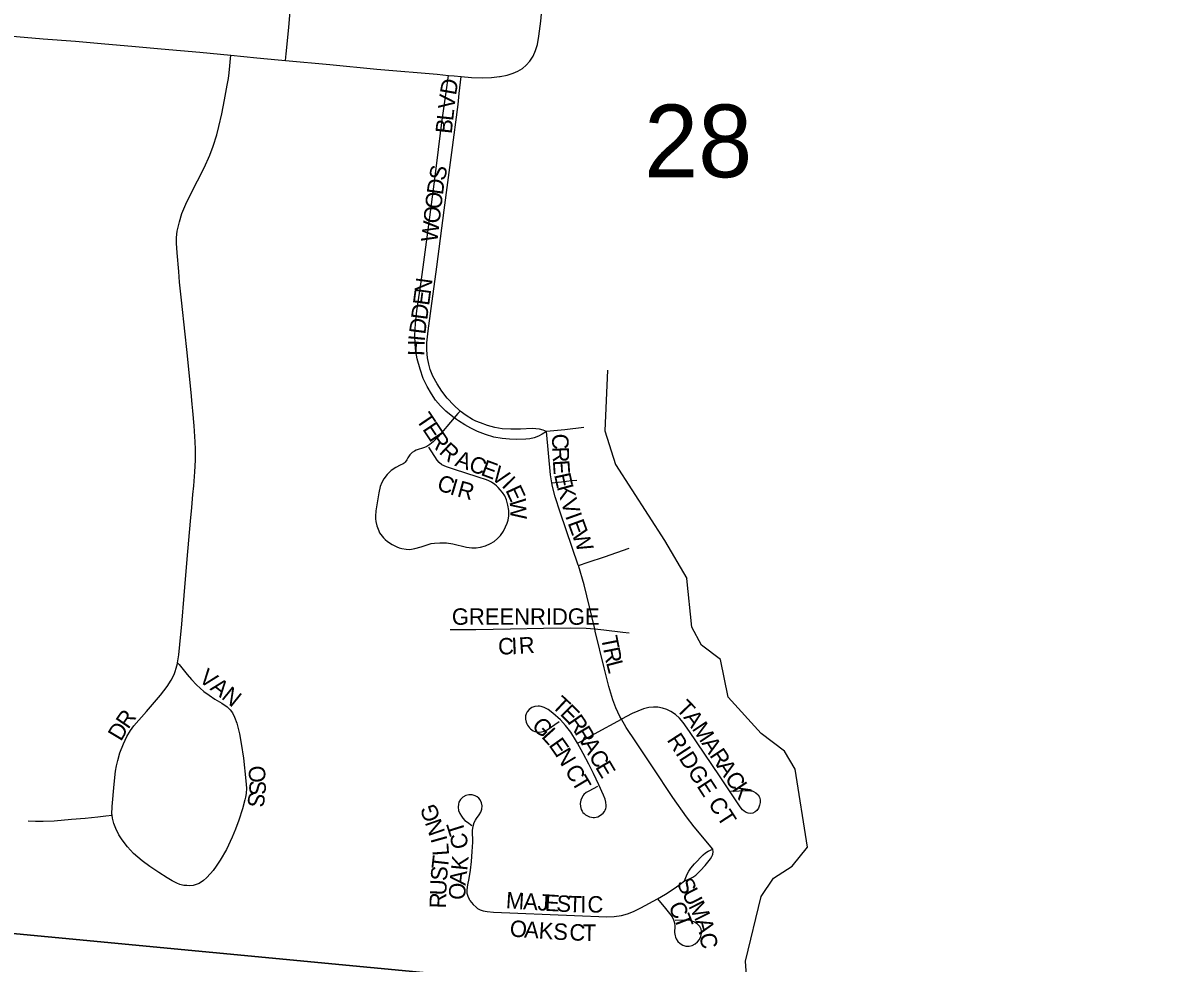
# Model space of a CAD drawing. Extents: x 1410790 to 1770854, y 448063 to 770588.
# Drawn here: x 1535566 to 1539019, y 639877 to 642738 of the extents above; entities that cross this region are included whole.
import ezdxf

# ---------------------------------------------------------------- set-up
doc = ezdxf.new("R2010")
doc.units = 0
for name, color, linetype in [('GM_X_City_Street', 7, 'Continuous'), ('GM_X_City_Street_Text', 7, 'Continuous'), ('GM_X_Minor_River', 7, 'Continuous'), ('GM_X_Section', 7, 'Continuous'), ('GM_X_Section_Text', 7, 'Continuous')]:
    doc.layers.add(name, color=color, linetype=linetype)

msp = doc.modelspace()

# ---------------------------------------------------------------- linework, layer by layer
at = {"layer": 'GM_X_City_Street'}
for points in [[(1536365.5, 642623), (1536367.5, 642643), (1536375.7, 642723.7), (1536382.9, 642812), (1536388.7, 642887.1), (1536391.7, 642922.9), (1536395.8, 642971.8), (1536399.7, 643011), (1536404.5, 643059.9), (1536404.9, 643064.8)], [(1537017, 642574.1), (1537018.4, 642574.3), (1537040.5, 642578.8), (1537058.8, 642584.5), (1537073.1, 642590.9), (1537086.5, 642599.1), (1537098.5, 642609.2), (1537108.8, 642621), (1537119.2, 642636.7), (1537126.8, 642654), (1537132.1, 642672.3), (1537136.9, 642697.7), (1537142.5, 642743), (1537148.9, 642811.9), (1537152, 642831.8), (1537158.1, 642854.6), (1537166.5, 642873.3), (1537173.8, 642884.8), (1537182.3, 642895.5), (1537195.2, 642906.9), (1537196.8, 642907.9)], [(1535441.9, 642704.9), (1535628.4, 642689.5), (1535726.5, 642681.6), (1535804.8, 642674.5), (1535909.3, 642665.3), (1535987.7, 642658.4), (1536105.4, 642648.5), (1536199.3, 642639.1)], [(1535837.9, 640327.4), (1535837.5, 640330.8), (1535838.1, 640353.7), (1535843.8, 640421.5), (1535848.8, 640460.8), (1535851.5, 640477.6), (1535855.1, 640493.4), (1535861.9, 640517.4), (1535872.3, 640544.1), (1535883.2, 640567.1), (1535894, 640584.8), (1535904.4, 640599), (1535942.7, 640642.9), (1535985.4, 640692.6), (1536005.5, 640718.6), (1536017.7, 640738), (1536026.4, 640755.7), (1536029.8, 640764.4), (1536032.9, 640774.2), (1536037, 640788.4), (1536037.3, 640790.9), (1536040.6, 640814.6), (1536043.8, 640846.7), (1536049.7, 640908.3), (1536057.4, 640995.8), (1536066.9, 641106.5), (1536076.8, 641221.4), (1536080.5, 641263.8), (1536084, 641302.9), (1536086.3, 641329.1), (1536090.1, 641371.5), (1536091.9, 641407.5), (1536091.8, 641440.3), (1536091.2, 641463.2), (1536088.9, 641495.9), (1536087.7, 641512.2), (1536083.2, 641557.8), (1536081.2, 641577.4), (1536078.2, 641613.3), (1536065.4, 641743.6), (1536060.1, 641791.1), (1536048.8, 641894.2), (1536043.2, 641948.7), (1536040.8, 641981.2), (1536035.7, 642038.3), (1536033.6, 642067.7), (1536033.6, 642084.7), (1536036.1, 642104.1), (1536042.8, 642132.7), (1536050.6, 642157.6), (1536062.8, 642186.1), (1536077.3, 642217.3), (1536117.8, 642296.2), (1536135.2, 642335.1), (1536145.9, 642362.6), (1536156.9, 642396.9), (1536163, 642422.4), (1536171.5, 642461), (1536180, 642503.7), (1536188.2, 642547.7), (1536192, 642568.4), (1536193.8, 642586.1), (1536199.3, 642639.1)], [(1536199.3, 642639.1), (1536278.4, 642631.3), (1536343.6, 642624.9), (1536365.5, 642623)], [(1536365.5, 642623), (1536500.4, 642610.8), (1536644, 642597.3), (1536655.6, 642596.3)], [(1536655.6, 642596.3), (1536827, 642581.3), (1536861.4, 642578)], [(1536879, 641535.8), (1536864.3, 641547.1), (1536853.6, 641556.2), (1536837.3, 641572.4), (1536822.6, 641590), (1536809.8, 641609), (1536796.9, 641631.8), (1536785, 641655.7), (1536775.2, 641683.9), (1536766.6, 641715.5), (1536762.7, 641737.5), (1536760, 641760.2), (1536759.4, 641786.4), (1536760.2, 641804.7), (1536761.5, 641823.5), (1536765.3, 641861.6), (1536776.3, 641936), (1536784.5, 641994.4), (1536804.7, 642147), (1536821, 642270.4), (1536841.3, 642435), (1536854.3, 642527.2), (1536861.4, 642578)], [(1536896.7, 641556.8), (1536896.6, 641556.9), (1536877.4, 641574.7), (1536857.3, 641596.4), (1536841.2, 641617.2), (1536826.9, 641639.1), (1536814.4, 641662.5), (1536806.3, 641683), (1536801.7, 641699.5), (1536797.7, 641718.8), (1536795.6, 641741.6), (1536796, 641764.6), (1536799.8, 641800.5), (1536809.3, 641868.7), (1536825.9, 641995.4), (1536848.4, 642167.7), (1536859.7, 642252.3), (1536871.6, 642343.4), (1536890.7, 642489.8), (1536894.5, 642522.3), (1536900.6, 642574.3)], [(1536861.4, 642578), (1536879.2, 642576.4), (1536900.6, 642574.3)], [(1536900.6, 642574.3), (1536931.2, 642571.4), (1536963.6, 642570.3), (1536992.8, 642571.4), (1537017, 642574.1)], [(1536879, 641535.8), (1536829.3, 641476.9), (1536814.6, 641462.7), (1536804.9, 641454.7), (1536796.2, 641448.9), (1536789.1, 641446.2), (1536763.7, 641437.5), (1536757.9, 641434.9), (1536750.9, 641430.8), (1536743.9, 641423.4), (1536737.7, 641414.3), (1536734.4, 641408.5), (1536729.8, 641401.1), (1536726.9, 641397.8), (1536723.7, 641395.7), (1536715, 641392.5), (1536701.4, 641385), (1536687, 641375.4), (1536680.8, 641370.2), (1536675.2, 641364.1), (1536665.2, 641351), (1536658.8, 641339.6), (1536654, 641327.4), (1536649.4, 641308.3), (1536640.5, 641253.2), (1536639.4, 641236.8), (1536639.5, 641228.7), (1536640.5, 641220.5), (1536643.4, 641207.6), (1536649.2, 641192.3), (1536651.9, 641186.7), (1536655.7, 641180.9), (1536664, 641170.8), (1536669.2, 641165.6), (1536676.3, 641159.9), (1536689.8, 641150.6), (1536704.5, 641143.2), (1536711.7, 641140.5), (1536720.1, 641138.3), (1536733.1, 641136.3), (1536741.8, 641136), (1536749.2, 641136.8), (1536759.1, 641138.5), (1536778.1, 641144.1), (1536799.9, 641151.2), (1536809.4, 641153.7), (1536819.2, 641155), (1536835.5, 641156.3), (1536855.2, 641155.4), (1536874.7, 641152.4), (1536916.2, 641142.5), (1536932.5, 641140.6), (1536945.6, 641140.6), (1536958.6, 641142.5), (1536974.3, 641147.1), (1536989.4, 641153.6), (1537000.7, 641160.3), (1537010.8, 641168.6), (1537019.4, 641178.5), (1537028.8, 641191.6), (1537035.4, 641204.4), (1537040, 641215.8), (1537043.2, 641225.2), (1537045.3, 641238.1), (1537045.7, 641245.6), (1537045.1, 641254.5), (1537042.7, 641270.7), (1537038.1, 641286.5), (1537032.8, 641298.5), (1537025.6, 641309.4), (1537019.3, 641317.4), (1537012.8, 641324.4), (1537007.8, 641328.9), (1537003, 641333), (1536992, 641340.3), (1536984.3, 641344.2), (1536977.2, 641347.3), (1536952.4, 641355.9), (1536911.7, 641368.9), (1536883.2, 641378), (1536855.2, 641386.7), (1536848.2, 641389.6), (1536841.6, 641393.3), (1536833.3, 641399.9), (1536826.7, 641407.1), (1536802, 641446.5)], [(1536896.7, 641556.8), (1536890.3, 641549.1), (1536879, 641535.8)], [(1537160.3, 641494.7), (1537146.3, 641486.2), (1537135.6, 641480.2), (1537122.7, 641474.9), (1537108.7, 641472.1), (1537096.7, 641471.2), (1537067.5, 641470.3), (1537047.2, 641470.8), (1537024.6, 641472.9), (1536999.4, 641477.7), (1536974.2, 641485.1), (1536949.8, 641494.7), (1536929.3, 641505), (1536911.4, 641514.8), (1536891.7, 641526.7), (1536885.7, 641531), (1536879, 641535.8)], [(1537160.3, 641494.7), (1537149.3, 641498.6), (1537139, 641501.5), (1537127, 641502.8), (1537116, 641503.2), (1537080.8, 641501.3), (1537051.3, 641501.2), (1537025.1, 641503), (1537002.4, 641506.8), (1536980.2, 641512.6), (1536958.6, 641520.4), (1536945.1, 641526.3), (1536934.8, 641531.5), (1536915, 641543.1), (1536896.7, 641556.8)], [(1537273.3, 641507.1), (1537215.4, 641499.8), (1537160.3, 641494.7)], [(1537176.3, 641338.5), (1537171.8, 641362.5), (1537160.3, 641494.7)], [(1537176.3, 641338.5), (1537205.7, 641341.7), (1537235.8, 641345), (1537252.5, 641346.9)], [(1537256.9, 641086.5), (1537256.5, 641087.9), (1537201.5, 641249.3), (1537186.4, 641295.9), (1537178.3, 641327.4), (1537176.3, 641338.5)], [(1537256.9, 641086.5), (1537286.8, 641096.6), (1537336.7, 641113.3), (1537411.3, 641139.6)], [(1537306.7, 640894.6), (1537274.5, 641028), (1537256.9, 641086.5)], [(1536866.5, 640892.3), (1536945.3, 640892.6), (1537050.3, 640894.2), (1537150.8, 640896), (1537233.6, 640896.9), (1537281, 640896), (1537306.7, 640894.6)], [(1537388, 640619.7), (1537383.3, 640627.7), (1537370.7, 640653.9), (1537361.7, 640678.1), (1537349.8, 640718.7), (1537335.3, 640775.9), (1537308.4, 640887.5), (1537306.7, 640894.6)], [(1537306.7, 640894.6), (1537334.4, 640891.4), (1537392.3, 640884.5), (1537411.6, 640881.8)], [(1536037.3, 640790.9), (1536042, 640785.2), (1536066.9, 640754.9), (1536079.7, 640740.3), (1536095.1, 640723.4), (1536117.1, 640703.9), (1536132.9, 640692.1), (1536150.6, 640680.7), (1536171.9, 640668), (1536187.8, 640656.5), (1536197.4, 640647.7), (1536204, 640638.2), (1536210.9, 640625.4), (1536217.3, 640606.8), (1536225.4, 640574.9), (1536230.7, 640545.4), (1536238.1, 640500.6), (1536245.4, 640432.1), (1536246.6, 640409.2), (1536245.6, 640392.8), (1536244.2, 640382.5), (1536242.2, 640373.5), (1536235.2, 640346.3), (1536223.9, 640312.4), (1536213.9, 640285.2), (1536203.5, 640259.9), (1536185.9, 640222.8), (1536167.3, 640190.7), (1536154.7, 640171.7), (1536145.2, 640159.4), (1536137.5, 640149.5), (1536125.7, 640136.8), (1536116.2, 640128.2), (1536103.1, 640119.7), (1536094, 640116), (1536085, 640113.8), (1536075, 640112.4), (1536065.1, 640112.9), (1536056.5, 640113.8), (1536044.3, 640116.5), (1536034.8, 640120.1), (1536020.3, 640127.3), (1536005.8, 640136.4), (1535980, 640152.7), (1535952.9, 640170.8), (1535929.3, 640188.9), (1535903.5, 640211.1), (1535885, 640230.5), (1535868.7, 640252.7), (1535858.3, 640268), (1535848.9, 640286.7), (1535842.8, 640301.9), (1535838.9, 640317.8), (1535837.9, 640327.4)], [(1537254.5, 640545.9), (1537251.2, 640551.9), (1537233.6, 640579.5), (1537217.7, 640600.3), (1537202.2, 640617.2), (1537179.4, 640637.4), (1537164.6, 640648.8), (1537153.1, 640655.1), (1537143.8, 640658.3), (1537138.5, 640659.2), (1537134.2, 640659.4), (1537124.5, 640658.2), (1537115.4, 640654.4), (1537107.5, 640648.7), (1537100.9, 640641.5), (1537097.7, 640635.8), (1537096, 640629.5), (1537095.9, 640619.7), (1537098, 640610.1), (1537099.8, 640605.5), (1537102.1, 640601), (1537107.9, 640593.1), (1537110.7, 640590.1), (1537115.2, 640586.6), (1537118.9, 640584.1), (1537123.9, 640582.2), (1537130.2, 640580.6), (1537139.9, 640580.1), (1537149.6, 640582), (1537155.7, 640584.4), (1537161.7, 640587.2), (1537198.7, 640612.7)], [(1537720.7, 640399.9), (1537771.1, 640401.9), (1537781.6, 640401.4), (1537785.5, 640401.1), (1537789.8, 640399.5), (1537797.3, 640395.6), (1537803.5, 640389.7), (1537807.8, 640382.4), (1537810, 640374.2), (1537810.4, 640369.9), (1537810, 640365.8), (1537808.1, 640357.3), (1537804.8, 640349.1), (1537799.7, 640341.5), (1537795.2, 640337.1), (1537787.5, 640333.1), (1537780, 640331.9), (1537773.1, 640333), (1537767.5, 640335.1), (1537761.5, 640339.1), (1537756.8, 640343.7), (1537748.7, 640353.1), (1537723.1, 640392.6), (1537686.2, 640446.7), (1537594.7, 640582.1), (1537575.7, 640609.2), (1537564.7, 640622), (1537552.1, 640633.4), (1537538, 640643), (1537525.6, 640648.9), (1537512.5, 640653.2), (1537499, 640655.7), (1537485.3, 640656), (1537471.7, 640654.5), (1537455.2, 640650.5), (1537420.4, 640636.9), (1537388, 640619.7)], [(1537254.5, 640545.9), (1537268.3, 640553.6), (1537306.3, 640575.1), (1537388, 640619.7)], [(1537665.9, 640223.9), (1537609.7, 640291.4), (1537585.7, 640322.4), (1537544.7, 640381.5), (1537482.7, 640474.1), (1537431.3, 640550.1), (1537402.8, 640593.9), (1537388, 640619.7)], [(1537315.2, 640414.1), (1537288.2, 640400.6), (1537281, 640396.6), (1537273.8, 640389.9), (1537270.6, 640385.9), (1537268.1, 640381.9), (1537264.3, 640372.8), (1537262.7, 640363.1), (1537263.3, 640353.3), (1537265.3, 640345), (1537267.9, 640339.7), (1537270.9, 640335.2), (1537274.3, 640331.9), (1537278.4, 640328.8), (1537286.9, 640323.9), (1537290.8, 640322.5), (1537296.3, 640321.1), (1537301.7, 640320.2), (1537306.1, 640320.7), (1537315.7, 640322.7), (1537324.6, 640327), (1537332.1, 640333.3), (1537336, 640338.5), (1537338.5, 640342.7), (1537340, 640347.4), (1537341.1, 640351.4), (1537341.6, 640357), (1537340.9, 640366.8), (1537338.6, 640376.4), (1537333.8, 640388.6), (1537319.4, 640419.3), (1537302.8, 640454.6), (1537288.6, 640482.7), (1537271.8, 640514.6), (1537254.5, 640545.9)], [(1536927, 640068), (1536925.3, 640070.8), (1536921, 640079.6), (1536918.5, 640089.1), (1536918.3, 640094), (1536918.3, 640098.9), (1536919.8, 640108.6), (1536920.6, 640114.9), (1536924.1, 640134.2), (1536928.2, 640160.1), (1536931.8, 640186.2), (1536934, 640216.4), (1536935.3, 640245), (1536935.1, 640281), (1536936.3, 640294.1), (1536939.7, 640304.7), (1536943.4, 640312.1), (1536946.7, 640317), (1536954.7, 640328.1), (1536959.7, 640336.6), (1536962.9, 640345.9), (1536963.7, 640355.6), (1536962.1, 640365.3), (1536958.2, 640374.2), (1536954, 640379.2), (1536949, 640383.4), (1536943.2, 640386.4), (1536933.7, 640389), (1536923.9, 640389.1), (1536914.3, 640386.8), (1536905.6, 640382.2), (1536898.5, 640375.5), (1536893.6, 640367.1), (1536891.6, 640360.9), (1536890.8, 640351.2), (1536892.3, 640341.5), (1536895.9, 640332.2), (1536900.9, 640323.8), (1536905.1, 640317.8), (1536911.7, 640311.5), (1536919.5, 640305.9), (1536933.1, 640295.6)], [(1535582.7, 640310.6), (1535604.9, 640309.2), (1535628.4, 640308.8), (1535661.5, 640310.1), (1535714, 640314.7), (1535756.5, 640318.7), (1535794.5, 640321.9), (1535819.4, 640325.1), (1535837.9, 640327.4)], [(1537579.3, 640127.8), (1537592.5, 640132.3), (1537605.3, 640138.9), (1537614.5, 640145.3), (1537628.8, 640159.5), (1537642.4, 640174.6), (1537658.5, 640194.6), (1537663.4, 640201.6), (1537664.6, 640205.3), (1537665.9, 640209), (1537666.7, 640215.6), (1537665.9, 640223.9)], [(1537579.3, 640127.8), (1537587.9, 640148), (1537592.9, 640156.6), (1537599, 640166), (1537610.3, 640179), (1537636.5, 640206.7), (1537644, 640213.1), (1537651.8, 640218.1), (1537665.9, 640223.9)], [(1537497.2, 640073.3), (1537521.7, 640086.9), (1537551.9, 640106), (1537566.5, 640117.5), (1537579.3, 640127.8)], [(1536927, 640068), (1536936.9, 640055.2), (1536945.7, 640047.3), (1536950, 640043.6), (1536957.9, 640039.5), (1536967.5, 640036.6), (1536979.7, 640034.2), (1536999, 640032.6), (1537244.9, 640021.6), (1537343.1, 640017.7), (1537365.5, 640018.9), (1537387.7, 640022.3), (1537406.3, 640027), (1537424.2, 640033.8), (1537447.2, 640045.5), (1537497.2, 640073.3)], [(1537497.2, 640073.3), (1537521.6, 640043.1), (1537542.1, 640017.7), (1537546.7, 640009.1), (1537549.4, 639999.7), (1537550.4, 639990), (1537549.8, 639970.4), (1537551, 639960.7), (1537552.1, 639956.6), (1537554.1, 639951.5), (1537559.4, 639943.3), (1537566.4, 639936.5), (1537574.4, 639931.5), (1537584.2, 639928.7), (1537593.9, 639928.5), (1537603.4, 639930.9), (1537612, 639935.5), (1537619.5, 639941.8), (1537625.5, 639949.5), (1537629.7, 639958.4), (1537631.8, 639968), (1537631.7, 639974.5), (1537630.2, 639980.7), (1537626.3, 639988.8), (1537622.6, 639992.9), (1537618.8, 639996.3), (1537610.6, 640001.7), (1537601.6, 640005.4), (1537592, 640007.4), (1537579.3, 640008.2), (1537551.6, 640007.3)]]:
    msp.add_lwpolyline(points, dxfattribs=at)
at = {"layer": 'GM_X_Minor_River'}
for points in [[(1537345.2, 641681.2), (1537337.5, 641497), (1537369.5, 641394.1), (1537519.1, 641162.6), (1537587.4, 641047.6)], [(1538011.6, 638773.2), (1538039.9, 638830), (1538024.4, 639069), (1537980.7, 639194.3), (1537993.2, 639324.3), (1537927.7, 639462.1), (1537805, 639643.3), (1537778.1, 639706), (1537765.5, 639882.7), (1537813.3, 640080.2), (1537850.4, 640135.5), (1537907.2, 640172.4), (1537954.4, 640229.5), (1537916.8, 640467), (1537883.8, 640521.8), (1537812.7, 640575.5), (1537712.7, 640686), (1537688.9, 640800.8), (1537631.6, 640844.1), (1537602.6, 640898.9), (1537587.4, 641047.6)]]:
    msp.add_lwpolyline(points, dxfattribs=at)
at = {"layer": 'GM_X_Section'}
for points in [[(1534609.1, 645459.7), (1540107.2, 644974.6), (1539587.8, 639581.9), (1534160.3, 640098.2)], [(1539587.8, 639581.9), (1539127, 634235.4), (1533718.1, 634783.3), (1534160.3, 640098.2)]]:
    msp.add_lwpolyline(points, close=True, dxfattribs=at)

# ---------------------------------------------------------------- texts
at = {"layer": 'GM_X_City_Street_Text'}
for s, rotation, p in [('D', 79.9952, (1536884.3, 642515.7)), ('V', 83.3521, (1536879.3, 642472.8)), ('L', 83.8326, (1536875.6, 642437.9)), ('B', 83.8207, (1536871.3, 642398.5)), ('S', 78.4891, (1536850.4, 642255.3)), ('D', 82.1512, (1536844.5, 642212.6)), ('O', 83.1755, (1536839.3, 642169.1)), ('O', 83.1755, (1536834.1, 642125.4)), ('W', 83.1752, (1536827.3, 642068.6)), ('N', 82.4032, (1536807.1, 641910.6)), ('E', 82.4051, (1536802.5, 641875.7)), ('D', 82.414, (1536796.7, 641832.1)), ('D', 82.5469, (1536791, 641788.5)), ('I', 84.1981, (1536788.8, 641767)), ('H', 88.4477, (1536787.7, 641724)), ('T', 303.7317, (1536761.3, 641530.9)), ('E', 303.7317, (1536780.8, 641501.7)), ('R', 303.7305, (1536800.4, 641472.4)), ('R', 316.7681, (1536830.4, 641430)), ('C', 272.1979, (1537176.1, 641487)), ('A', 340.8308, (1536878.7, 641391.1)), ('R', 272.2142, (1537177.6, 641447.4)), ('C', 339.66, (1536920, 641376.7)), ('E', 339.655, (1536957.1, 641363)), ('V', 324.564, (1536987.1, 641352.3)), ('E', 273.7491, (1537179.2, 641406.4)), ('C', 340.6974, (1536823.2, 641318.1)), ('I', 314.691, (1537021.2, 641328.3)), ('E', 282.4729, (1537182.7, 641363)), ('I', 343.4695, (1536863.1, 641304.2)), ('R', 344.7597, (1536885.4, 641297.6)), ('E', 294.8419, (1537034.1, 641316.4)), ('K', 285.1231, (1537190.9, 641326.2)), ('W', 272.43, (1537047.6, 641289.5)), ('V', 286.7253, (1537202.8, 641282.3)), ('I', 289.597, (1537216.3, 641237.6)), ('E', 289.9334, (1537223.8, 641216.5)), ('W', 289.9847, (1537235.8, 641183.4)), ('GREENRIDGE', 0, (1536871.9, 640906.5)), ('T', 281.1599, (1537325.5, 640868)), ('C', 0.8015, (1537012.8, 640816.1)), ('I', 2.5658, (1537054.1, 640816.7)), ('R', 3.6215, (1537077.1, 640817.8)), ('R', 281.1552, (1537332.3, 640833.5)), ('V', 322.2209, (1536098.8, 640737.4)), ('L', 284.5302, (1537340.7, 640791.5)), ('A', 322.2231, (1536133.6, 640710.4)), ('N', 321.1081, (1536168.1, 640683.6)), ('T', 317.1161, (1537173, 640657.7)), ('E', 315.029, (1537198.4, 640634.1)), ('T', 313.7828, (1537551.5, 640648.8)), ('R', 55.6566, (1535887.1, 640586.8)), ('R', 304.8488, (1537221.8, 640611)), ('A', 307.0622, (1537574.9, 640624.6)), ('D', 59.0419, (1535864.9, 640549.7)), ('G', 313.578, (1537112.2, 640596.8)), ('R', 300.9575, (1537243.9, 640579.3)), ('M', 303.6118, (1537600.9, 640590.1)), ('L', 312.0624, (1537142.3, 640565.2)), ('E', 305.1487, (1537164.9, 640540.3)), ('RIDGE CT', 302.949, (1537524.7, 640556.3)), ('N', 301.0162, (1537184.7, 640512.3)), ('A', 300.7726, (1537264.3, 640545.4)), ('A', 303.5113, (1537630.1, 640546.1)), ('R', 303.519, (1537654.4, 640509.4)), ('C', 300.7745, (1537286.8, 640507.6)), ('E', 300.7866, (1537307, 640473.6)), ('O', 275.0015, (1536252, 640475.8)), ('C', 300.6952, (1537214.1, 640463.3)), ('A', 303.5209, (1537676.3, 640476.4)), ('S', 269.6858, (1536255.8, 640433.2)), ('T', 300.6616, (1537234.3, 640429.3)), ('C', 303.5116, (1537700.6, 640439.7)), ('K', 303.5022, (1537722.5, 640406.7)), ('S', 260.4748, (1536255.8, 640400.1)), ('G', 109.0363, (1536837.8, 640317.5)), ('N', 109.1251, (1536852.2, 640275.9)), ('T', 107.4241, (1536914.3, 640274.7)), ('I', 105.6718, (1536859.2, 640251.6)), ('C', 100.5697, (1536923.2, 640229.5)), ('L', 94.1746, (1536863.6, 640205.7)), ('T', 83.6342, (1536859.5, 640160.7)), ('K', 84.4515, (1536918.7, 640157.2)), ('S', 85.1456, (1536856.6, 640126)), ('A', 83.2736, (1536913.5, 640112.4)), ('U', 87.9436, (1536855, 640082.7)), ('O', 89.6065, (1536913.3, 640069.8)), ('S', 296.8339, (1537554.7, 640121.4)), ('R', 87.9355, (1536853.6, 640043.1)), ('M', 356.4458, (1537035.2, 640044.1)), ('A', 356.4353, (1537087.9, 640040.9)), ('J', 356.4608, (1537131.9, 640038.1)), ('E', 356.4458, (1537153.8, 640036.8)), ('S', 356.4458, (1537189, 640034.6)), ('T', 357.983, (1537225.6, 640032.3)), ('I', 359.7738, (1537262.5, 640031)), ('C', 359.9703, (1537284.6, 640031)), ('U', 296.832, (1537570.6, 640090)), ('C', 297.6511, (1537528.7, 640049)), ('M', 296.8339, (1537590.5, 640050.7)), ('T', 291.1925, (1537546.4, 640015.3)), ('O', 356.0849, (1537047, 639958.3)), ('A', 356.1023, (1537091, 639955.3)), ('K', 356.1757, (1537134.9, 639952.3)), ('S', 356.7473, (1537179.4, 639949.3)), ('C', 357.9147, (1537228.8, 639946.6)), ('T', 359.7191, (1537270.1, 639945.1)), ('A', 285.3615, (1537613.3, 640006.1)), ('C', 280.3049, (1537624.7, 639964.8))]:
    msp.add_text(s, height=50, rotation=rotation, dxfattribs=at).set_placement(p)
at = {"layer": 'GM_X_Section_Text'}
msp.add_text('28', height=221, rotation=0, dxfattribs=at).set_placement((1537457.1, 642268))

doc.saveas('drawing.dxf')
